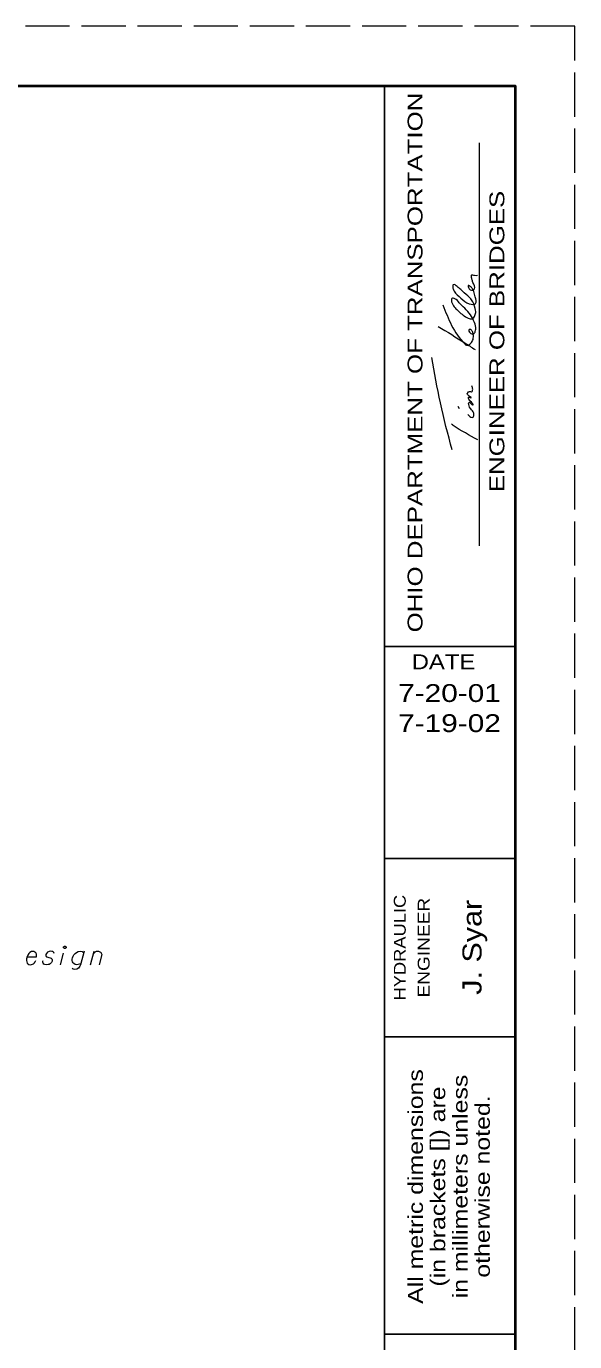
# Model space of a CAD drawing. Extents: x 1083.1 to 1117.1, y 697.4 to 741.4.
# Drawn here: x 1112.51 to 1117.13, y 730.29 to 741.35 of the extents above; entities that cross this region are included whole.
import ezdxf
from ezdxf.enums import TextEntityAlignment as Align

# ---------------------------------------------------------------- set-up
doc = ezdxf.new("R2010")
doc.units = 0
doc.header["$LTSCALE"] = 0.062
doc.linetypes.add('LONG_DASHED', pattern=[7.5, 6, -1.5])
doc.layers.add('1', color=7, linetype='Continuous', lineweight=13)

msp = doc.modelspace()

# ---------------------------------------------------------------- linework, layer by layer
at = {"layer": '1', "lineweight": 25}
for p, q in [((1085.12642, 740.85408), (1116.62642, 740.85408)), ((1115.52642, 719.85408), (1115.52642, 740.85408)), ((1116.62642, 740.85408), (1116.62642, 719.85408)), ((1116.62642, 736.13825), (1115.52642, 736.13825)), ((1116.62642, 734.35408), (1115.52642, 734.35408)), ((1116.62642, 732.85408), (1115.52642, 732.85408)), ((1116.62642, 730.35408), (1115.52642, 730.35408))]:
    msp.add_line(p, q, dxfattribs=at)
at = {"layer": '1'}
for p, q in [((1116.32517, 736.98508), (1116.32517, 740.37517)), ((1116.15767, 738.136), (1116.1475, 738.15525)), ((1112.80075, 733.46108), (1112.82683, 733.559)), ((1113.0535, 733.46108), (1113.0845, 733.57508))]:
    msp.add_line(p, q, dxfattribs=at)
at = {"layer": '1', "linetype": 'LONG_DASHED'}
msp.add_lwpolyline([(1083.12642, 719.35408), (1117.12642, 719.35408), (1117.12642, 741.35408), (1083.12642, 741.35408)], close=True, dxfattribs=at)
at = {"layer": '1', "lineweight": 40}
msp.add_lwpolyline([(1085.12642, 740.85408), (1116.62642, 740.85408), (1116.62642, 719.85408), (1085.12642, 719.85408)], close=True, dxfattribs=at)
at = {"layer": '1'}
msp.add_lwpolyline([(1112.8355, 733.61842), (1112.84167, 733.61842), (1112.84542, 733.616), (1112.84908, 733.611), (1112.84908, 733.60483), (1112.84542, 733.59983), (1112.84167, 733.59742), (1112.8355, 733.59742), (1112.83175, 733.59983), (1112.828, 733.60483), (1112.828, 733.611), (1112.83175, 733.616)], close=True, dxfattribs=at)
for points in [[(1112.52083, 733.52675), (1112.60008, 733.52675), (1112.60133, 733.53917), (1112.59883, 733.55033), (1112.59392, 733.5615), (1112.579, 733.57258), (1112.56667, 733.57383), (1112.55675, 733.57142), (1112.54308, 733.56392), (1112.53442, 733.55525), (1112.527, 733.54167), (1112.52208, 733.53175), (1112.51708, 733.51067), (1112.51708, 733.49708), (1112.51833, 733.48592), (1112.52208, 733.476), (1112.53692, 733.46233), (1112.54683, 733.46108), (1112.55675, 733.46233), (1112.558, 733.46233), (1112.57408, 733.46983), (1112.58275, 733.4785), (1112.5865, 733.48467), (1112.58767, 733.48592), (1112.59392, 733.49708)], [(1112.74875, 733.5565), (1112.745, 733.56517), (1112.73633, 733.57142), (1112.72892, 733.57383), (1112.71775, 733.57508), (1112.70783, 733.57383), (1112.693, 733.56642), (1112.68308, 733.5565), (1112.67933, 733.54783), (1112.67808, 733.53792), (1112.68058, 733.53175), (1112.68558, 733.528), (1112.688, 733.52675), (1112.6955, 733.52433), (1112.70417, 733.52308), (1112.7165, 733.52058), (1112.724, 733.51808), (1112.73017, 733.51067), (1112.73267, 733.502), (1112.73142, 733.49083), (1112.72642, 733.48092), (1112.7165, 733.46983), (1112.70783, 733.46483), (1112.69792, 733.46233), (1112.68558, 733.46108), (1112.67067, 733.46233), (1112.66075, 733.46733), (1112.65583, 733.4735), (1112.65333, 733.48217), (1112.65333, 733.49083), (1112.65708, 733.49825)], [(1113.00025, 733.57508), (1112.96925, 733.46108), (1112.96433, 733.45), (1112.95933, 733.44008), (1112.95317, 733.43383), (1112.94075, 733.42517), (1112.92217, 733.42025), (1112.90733, 733.42392), (1112.89992, 733.42892)], [(1112.97175, 733.46983), (1112.96308, 733.46608), (1112.95192, 733.46233), (1112.93708, 733.46108), (1112.92467, 733.46233), (1112.91475, 733.471), (1112.90858, 733.4785), (1112.90358, 733.48592), (1112.90117, 733.49583), (1112.90117, 733.50942), (1112.90358, 733.52058), (1112.90733, 733.53425), (1112.91475, 733.54533), (1112.92592, 733.5565), (1112.93708, 733.56517), (1112.95192, 733.57258), (1112.96675, 733.57508), (1112.98417, 733.57142), (1112.9965, 733.5615)], [(1113.07708, 733.54783), (1113.08075, 733.554), (1113.08575, 733.5615), (1113.08942, 733.56517), (1113.09442, 733.57017), (1113.09933, 733.57258), (1113.1055, 733.57508), (1113.11175, 733.57633), (1113.11667, 733.57633), (1113.12292, 733.57508), (1113.12783, 733.57258), (1113.13275, 733.57017), (1113.13775, 733.56642), (1113.14267, 733.5615), (1113.14517, 733.55775), (1113.14767, 733.55283), (1113.15017, 733.54658), (1113.12783, 733.46108)]]:
    msp.add_lwpolyline(points, dxfattribs=at)
for points in [[(1116.01825, 739.01108), (1116.20142, 738.68275), (1116.21658, 738.67217), (1116.22675, 738.67217), (1116.25867, 738.69583), (1116.27375, 738.73), (1116.26875, 738.78125), (1116.25183, 738.80308), (1116.23833, 738.80308), (1116.23658, 738.79008), (1116.24675, 738.77492), (1116.26025, 738.7665), (1116.27533, 738.7665), (1116.2905, 738.78808), (1116.29392, 738.80742), (1116.28367, 738.86275), (1116.20142, 738.98317), (1116.15592, 739.02783), (1116.119, 739.06242), (1116.09383, 739.06458), (1116.09558, 739.026), (1116.12075, 738.98725), (1116.188, 738.92492), (1116.23008, 738.8995), (1116.26375, 738.895), (1116.28708, 738.921), (1116.29392, 738.95517), (1116.28883, 738.98092), (1116.25867, 739.05408), (1116.22842, 739.08608), (1116.16783, 739.1395), (1116.13917, 739.16533), (1116.10567, 739.18058), (1116.10225, 739.15258), (1116.11233, 739.12675), (1116.1695, 739.06683), (1116.24017, 739.01958), (1116.29217, 739.02192), (1116.2905, 739.07958), (1116.27867, 739.1225), (1116.26533, 739.14825), (1116.25517, 739.159), (1116.23175, 739.174), (1116.2335, 739.15692), (1116.26875, 739.13542), (1116.28367, 739.14617), (1116.27058, 739.19983), (1116.262, 739.22775), (1116.25867, 739.24042), (1116.25867, 739.25325), (1116.25867, 739.26192), (1116.28367, 739.25975), (1116.30908, 739.25975)], [(1115.97942, 738.82883), (1116.20317, 738.69133), (1116.28883, 738.63567)], [(1116.09567, 737.79183), (1115.997, 738.18708), (1115.92575, 738.56942)], [(1116.22675, 738.09075), (1116.235, 738.08008), (1116.27217, 738.06717), (1116.27692, 738.09958), (1116.25183, 738.136), (1116.23658, 738.17225), (1116.23658, 738.1915), (1116.25183, 738.18525), (1116.262, 738.17442), (1116.27217, 738.17008), (1116.2485, 738.20225), (1116.23658, 738.21725), (1116.2335, 738.23458), (1116.25692, 738.228), (1116.2485, 738.23667), (1116.22333, 738.2645), (1116.2335, 738.27967), (1116.25025, 738.28167), (1116.25867, 738.27967), (1116.26875, 738.301), (1116.262, 738.32892)], [(1116.31083, 737.87625), (1116.10567, 737.99625), (1116.09008, 738.00667)]]:
    msp.add_spline(points, degree=3, dxfattribs=at)

# ---------------------------------------------------------------- texts
for s, height, width, p in [('OHIO DEPARTMENT OF TRANSPORTATION', 0.125, 1.3, (1115.84633, 738.52633)), ('ENGINEER OF BRIDGES', 0.125, 1.3, (1116.53467, 738.70312)), ('HYDRAULIC', 0.1, 1.15, (1115.7055, 733.60517)), ('ENGINEER', 0.1, 1.2, (1115.90642, 733.60521)), ('J. Syar', 0.16, 1.2, (1116.34283, 733.60821)), ('All metric dimensions', 0.125, 1.25, (1115.85025, 731.59617)), ('in millimeters unless', 0.125, 1.25, (1116.22525, 731.59621)), ('(in brackets []) are', 0.125, 1.25, (1116.03775, 731.59617)), ('otherwise noted.', 0.125, 1.25, (1116.41275, 731.59617))]:
    msp.add_text(s, height=height, rotation=90, dxfattribs=dict(at, width=width)).set_placement(p, align=Align.CENTER)
for s, height, width, p in [('DATE', 0.125, 1.2, (1116.02312, 735.94683)), ('7-20-01', 0.15, 1.25, (1116.07346, 735.67133)), ('7-19-02', 0.15, 1.25, (1116.07346, 735.41825))]:
    msp.add_text(s, height=height, dxfattribs=dict(at, width=width)).set_placement(p, align=Align.CENTER)

doc.saveas('drawing.dxf')
